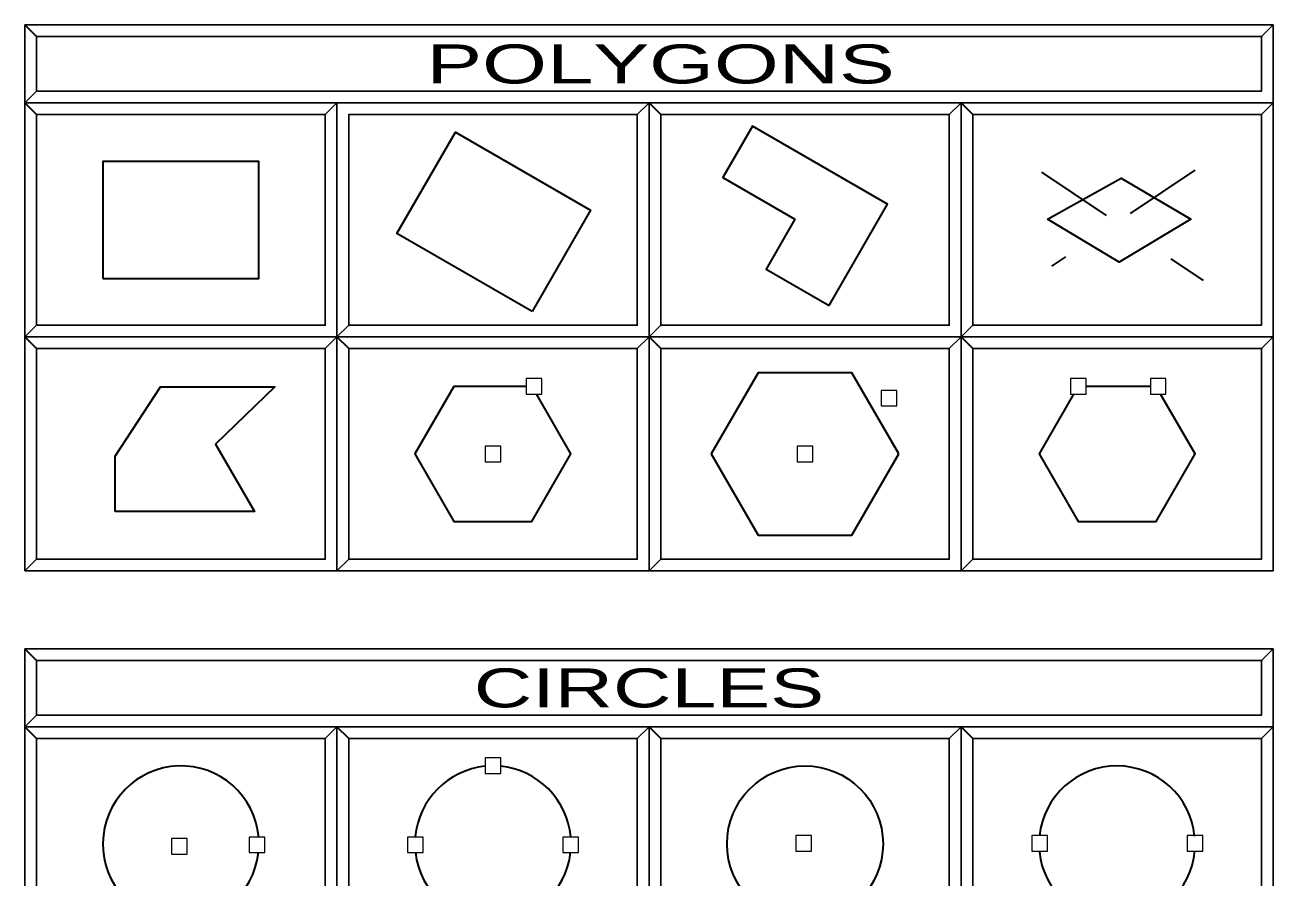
# Model space of a CAD drawing. Extents: x 95906.9 to 95918.9, y 90964.8 to 90972.9.
# Drawn here: x 95910.832 to 95912.432, y 90969.669 to 90970.762 of the extents above; entities that cross this region are included whole.
import ezdxf
from ezdxf.enums import TextEntityAlignment as Align

# ---------------------------------------------------------------- set-up
doc = ezdxf.new("R2010")
doc.units = 0
doc.header["$LTSCALE"] = 0.019
doc.linetypes.add('MEDIUM_DASHED', pattern=[4.5, 3, -1.5])
for name, color, linetype, lineweight in [('1', 7, 'Continuous', 25), ('11', 7, 'Continuous', 25), ('12', 7, 'Continuous', 25), ('17', 7, 'Continuous', 25), ('2', 7, 'Continuous', 13), ('3', 7, 'Continuous', 25), ('4', 7, 'Continuous', 35), ('6', 7, 'Continuous', 35), ('7', 7, 'Continuous', 35)]:
    doc.layers.add(name, color=color, linetype=linetype, lineweight=lineweight)

msp = doc.modelspace()

# ---------------------------------------------------------------- linework, layer by layer
at = {"layer": '1'}
for points in [[(95910.8318, 90970.6617), (95912.4318, 90970.6617), (95912.4318, 90970.7617), (95910.8318, 90970.7617)], [(95910.8318, 90970.3617), (95911.2318, 90970.3617), (95911.2318, 90970.6617), (95910.8318, 90970.6617)], [(95911.2318, 90970.3617), (95911.6318, 90970.3617), (95911.6318, 90970.6617), (95911.2318, 90970.6617)], [(95911.6318, 90970.3617), (95912.0318, 90970.3617), (95912.0318, 90970.6617), (95911.6318, 90970.6617)], [(95912.0318, 90970.3617), (95912.4318, 90970.3617), (95912.4318, 90970.6617), (95912.0318, 90970.6617)], [(95910.8318, 90970.0617), (95911.2318, 90970.0617), (95911.2318, 90970.3617), (95910.8318, 90970.3617)], [(95911.2318, 90970.0617), (95911.6318, 90970.0617), (95911.6318, 90970.3617), (95911.2318, 90970.3617)], [(95911.6318, 90970.0617), (95912.0318, 90970.0617), (95912.0318, 90970.3617), (95911.6318, 90970.3617)], [(95912.0318, 90970.0617), (95912.4318, 90970.0617), (95912.4318, 90970.3617), (95912.0318, 90970.3617)], [(95910.8318, 90969.8617), (95912.4318, 90969.8617), (95912.4318, 90969.9617), (95910.8318, 90969.9617)], [(95910.8318, 90969.5617), (95911.2318, 90969.5617), (95911.2318, 90969.8617), (95910.8318, 90969.8617)], [(95911.2318, 90969.5617), (95911.6318, 90969.5617), (95911.6318, 90969.8617), (95911.2318, 90969.8617)], [(95911.6318, 90969.5617), (95912.0318, 90969.5617), (95912.0318, 90969.8617), (95911.6318, 90969.8617)], [(95912.0318, 90969.5617), (95912.4318, 90969.5617), (95912.4318, 90969.8617), (95912.0318, 90969.8617)]]:
    msp.add_lwpolyline(points, close=True, dxfattribs=at)
at = {"layer": '11'}
for points in [[(95910.8468, 90970.3767), (95911.2168, 90970.3767), (95911.2168, 90970.6467), (95910.8468, 90970.6467)], [(95911.2468, 90970.3767), (95911.6168, 90970.3767), (95911.6168, 90970.6467), (95911.2468, 90970.6467)], [(95911.6468, 90970.3767), (95912.0168, 90970.3767), (95912.0168, 90970.6467), (95911.6468, 90970.6467)], [(95912.0468, 90970.3767), (95912.4168, 90970.3767), (95912.4168, 90970.6467), (95912.0468, 90970.6467)], [(95910.8468, 90970.0767), (95911.2168, 90970.0767), (95911.2168, 90970.3467), (95910.8468, 90970.3467)], [(95911.2468, 90970.0767), (95911.6168, 90970.0767), (95911.6168, 90970.3467), (95911.2468, 90970.3467)], [(95911.6468, 90970.0767), (95912.0168, 90970.0767), (95912.0168, 90970.3467), (95911.6468, 90970.3467)], [(95912.0468, 90970.0767), (95912.4168, 90970.0767), (95912.4168, 90970.3467), (95912.0468, 90970.3467)], [(95910.8468, 90969.5767), (95911.2168, 90969.5767), (95911.2168, 90969.8467), (95910.8468, 90969.8467)], [(95911.2468, 90969.5767), (95911.6168, 90969.5767), (95911.6168, 90969.8467), (95911.2468, 90969.8467)], [(95911.6468, 90969.5767), (95912.0168, 90969.5767), (95912.0168, 90969.8467), (95911.6468, 90969.8467)], [(95912.0468, 90969.5767), (95912.4168, 90969.5767), (95912.4168, 90969.8467), (95912.0468, 90969.8467)]]:
    msp.add_lwpolyline(points, close=True, dxfattribs=at)
at = {"layer": '12'}
for points in [[(95910.8468, 90970.3767), (95911.2168, 90970.3767), (95911.2168, 90970.6467), (95910.8468, 90970.6467)], [(95910.8468, 90969.5767), (95911.2168, 90969.5767), (95911.2168, 90969.8467), (95910.8468, 90969.8467)]]:
    msp.add_lwpolyline(points, close=True, dxfattribs=at)
at = {"layer": '17'}
for points in [[(95910.8468, 90970.6767), (95912.4168, 90970.6767), (95912.4168, 90970.7467), (95910.8468, 90970.7467)], [(95910.8468, 90969.8767), (95912.4168, 90969.8767), (95912.4168, 90969.9467), (95910.8468, 90969.9467)]]:
    msp.add_lwpolyline(points, close=True, dxfattribs=at)
at = {"layer": '2'}
for points in [[(95910.8318, 90970.7617), (95910.8318, 90970.6617), (95910.8468, 90970.6767), (95910.8468, 90970.7467), (95912.4168, 90970.7467), (95912.4318, 90970.7617)], [(95910.8318, 90970.6617), (95910.8318, 90970.3617), (95910.8468, 90970.3767), (95910.8468, 90970.6467), (95911.2168, 90970.6467), (95911.2318, 90970.6617)], [(95911.2318, 90970.6617), (95911.2318, 90970.3617), (95911.2468, 90970.3767), (95911.2468, 90970.6467), (95911.6168, 90970.6467), (95911.6318, 90970.6617)], [(95911.6318, 90970.6617), (95911.6318, 90970.3617), (95911.6468, 90970.3767), (95911.6468, 90970.6467), (95912.0168, 90970.6467), (95912.0318, 90970.6617)], [(95912.0318, 90970.6617), (95912.0318, 90970.3617), (95912.0468, 90970.3767), (95912.0468, 90970.6467), (95912.4168, 90970.6467), (95912.4318, 90970.6617)], [(95910.8318, 90970.3617), (95910.8318, 90970.0617), (95910.8468, 90970.0767), (95910.8468, 90970.3467), (95911.2168, 90970.3467), (95911.2318, 90970.3617)], [(95911.2318, 90970.3617), (95911.2318, 90970.0617), (95911.2468, 90970.0767), (95911.2468, 90970.3467), (95911.6168, 90970.3467), (95911.6318, 90970.3617)], [(95911.6318, 90970.3617), (95911.6318, 90970.0617), (95911.6468, 90970.0767), (95911.6468, 90970.3467), (95912.0168, 90970.3467), (95912.0318, 90970.3617)], [(95912.0318, 90970.3617), (95912.0318, 90970.0617), (95912.0468, 90970.0767), (95912.0468, 90970.3467), (95912.4168, 90970.3467), (95912.4318, 90970.3617)], [(95910.8318, 90969.9617), (95910.8318, 90969.8617), (95910.8468, 90969.8767), (95910.8468, 90969.9467), (95912.4168, 90969.9467), (95912.4318, 90969.9617)], [(95910.8318, 90969.8617), (95910.8318, 90969.5617), (95910.8468, 90969.5767), (95910.8468, 90969.8467), (95911.2168, 90969.8467), (95911.2318, 90969.8617)], [(95911.2318, 90969.8617), (95911.2318, 90969.5617), (95911.2468, 90969.5767), (95911.2468, 90969.8467), (95911.6168, 90969.8467), (95911.6318, 90969.8617)], [(95911.6318, 90969.8617), (95911.6318, 90969.5617), (95911.6468, 90969.5767), (95911.6468, 90969.8467), (95912.0168, 90969.8467), (95912.0318, 90969.8617)], [(95912.0318, 90969.8617), (95912.0318, 90969.5617), (95912.0468, 90969.5767), (95912.0468, 90969.8467), (95912.4168, 90969.8467), (95912.4318, 90969.8617)]]:
    msp.add_lwpolyline(points, close=True, dxfattribs=at)
at = {"layer": '3'}
for points in [[(95910.8318, 90970.6617), (95912.4318, 90970.6617), (95912.4318, 90970.7617), (95912.4168, 90970.7467), (95912.4168, 90970.6767), (95910.8468, 90970.6767)], [(95910.8318, 90970.3617), (95911.2318, 90970.3617), (95911.2318, 90970.6617), (95911.2168, 90970.6467), (95911.2168, 90970.3767), (95910.8468, 90970.3767)], [(95911.2318, 90970.3617), (95911.6318, 90970.3617), (95911.6318, 90970.6617), (95911.6168, 90970.6467), (95911.6168, 90970.3767), (95911.2468, 90970.3767)], [(95911.6318, 90970.3617), (95912.0318, 90970.3617), (95912.0318, 90970.6617), (95912.0168, 90970.6467), (95912.0168, 90970.3767), (95911.6468, 90970.3767)], [(95912.0318, 90970.3617), (95912.4318, 90970.3617), (95912.4318, 90970.6617), (95912.4168, 90970.6467), (95912.4168, 90970.3767), (95912.0468, 90970.3767)], [(95910.8318, 90970.0617), (95911.2318, 90970.0617), (95911.2318, 90970.3617), (95911.2168, 90970.3467), (95911.2168, 90970.0767), (95910.8468, 90970.0767)], [(95911.2318, 90970.0617), (95911.6318, 90970.0617), (95911.6318, 90970.3617), (95911.6168, 90970.3467), (95911.6168, 90970.0767), (95911.2468, 90970.0767)], [(95911.6318, 90970.0617), (95912.0318, 90970.0617), (95912.0318, 90970.3617), (95912.0168, 90970.3467), (95912.0168, 90970.0767), (95911.6468, 90970.0767)], [(95912.0318, 90970.0617), (95912.4318, 90970.0617), (95912.4318, 90970.3617), (95912.4168, 90970.3467), (95912.4168, 90970.0767), (95912.0468, 90970.0767)], [(95910.8318, 90969.8617), (95912.4318, 90969.8617), (95912.4318, 90969.9617), (95912.4168, 90969.9467), (95912.4168, 90969.8767), (95910.8468, 90969.8767)], [(95910.8318, 90969.5617), (95911.2318, 90969.5617), (95911.2318, 90969.8617), (95911.2168, 90969.8467), (95911.2168, 90969.5767), (95910.8468, 90969.5767)], [(95911.2318, 90969.5617), (95911.6318, 90969.5617), (95911.6318, 90969.8617), (95911.6168, 90969.8467), (95911.6168, 90969.5767), (95911.2468, 90969.5767)], [(95911.6318, 90969.5617), (95912.0318, 90969.5617), (95912.0318, 90969.8617), (95912.0168, 90969.8467), (95912.0168, 90969.5767), (95911.6468, 90969.5767)], [(95912.0318, 90969.5617), (95912.4318, 90969.5617), (95912.4318, 90969.8617), (95912.4168, 90969.8467), (95912.4168, 90969.5767), (95912.0468, 90969.5767)]]:
    msp.add_lwpolyline(points, close=True, dxfattribs=at)
at = {"layer": '4'}
for p, q in [((95910.8468, 90970.7467), (95910.8318, 90970.7617)), ((95910.8468, 90970.6467), (95910.8318, 90970.6617)), ((95911.6468, 90970.6467), (95911.6318, 90970.6617)), ((95912.0468, 90970.6467), (95912.0318, 90970.6617)), ((95910.8468, 90970.3467), (95910.8318, 90970.3617)), ((95911.2468, 90970.3467), (95911.2318, 90970.3617)), ((95911.6468, 90970.3467), (95911.6318, 90970.3617)), ((95912.0468, 90970.3467), (95912.0318, 90970.3617)), ((95910.8468, 90969.9467), (95910.8318, 90969.9617)), ((95910.8468, 90969.8467), (95910.8318, 90969.8617)), ((95911.2468, 90969.8467), (95911.2318, 90969.8617)), ((95911.6468, 90969.8467), (95911.6318, 90969.8617)), ((95912.0468, 90969.8467), (95912.0318, 90969.8617))]:
    msp.add_line(p, q, dxfattribs=at)
at = {"layer": '6', "linetype": 'MEDIUM_DASHED'}
for p, q in [((95912.1349, 90970.5731), (95912.3422, 90970.434)), ((95912.3317, 90970.5757), (95912.148, 90970.4524))]:
    msp.add_line(p, q, dxfattribs=at)
at = {"layer": '6'}
msp.add_line((95912.2746, 90970.2983), (95912.1929, 90970.2983), dxfattribs=at)
for points in [[(95911.4819, 90970.3944), (95911.3087, 90970.4944), (95911.3837, 90970.6243), (95911.5569, 90970.5243)], [(95911.8627, 90970.4021), (95911.9377, 90970.532), (95911.7645, 90970.632), (95911.7264, 90970.566), (95911.8188, 90970.5127), (95911.7819, 90970.4488)], [(95910.9318, 90970.4367), (95911.1318, 90970.4367), (95911.1318, 90970.5867), (95910.9318, 90970.5867)], [(95912.1428, 90970.5127), (95912.2372, 90970.5652), (95912.3264, 90970.5127), (95912.2346, 90970.4576)], [(95911.952, 90970.2117), (95911.8919, 90970.3158), (95911.7717, 90970.3158), (95911.7116, 90970.2117), (95911.7717, 90970.1076), (95911.8919, 90970.1076)], [(95910.9476, 90970.1378), (95910.9476, 90970.2087), (95911.0054, 90970.2979), (95911.1523, 90970.2979), (95911.0762, 90970.2244), (95911.126, 90970.1378)]]:
    msp.add_lwpolyline(points, close=True, dxfattribs=at)
at = {"layer": '6', "lineweight": 13}
for points in [[(95911.4743, 90970.2883), (95911.4943, 90970.2883), (95911.4943, 90970.3083), (95911.4743, 90970.3083)], [(95912.1722, 90970.2883), (95912.1922, 90970.2883), (95912.1922, 90970.3083), (95912.1722, 90970.3083)], [(95912.2745, 90970.2883), (95912.2945, 90970.2883), (95912.2945, 90970.3083), (95912.2745, 90970.3083)], [(95911.9294, 90970.2732), (95911.9494, 90970.2732), (95911.9494, 90970.2932), (95911.9294, 90970.2932)], [(95911.4218, 90970.2017), (95911.4418, 90970.2017), (95911.4418, 90970.2217), (95911.4218, 90970.2217)], [(95911.8218, 90970.2017), (95911.8418, 90970.2017), (95911.8418, 90970.2217), (95911.8218, 90970.2217)], [(95911.4217, 90969.8019), (95911.4417, 90969.8019), (95911.4417, 90969.8219), (95911.4217, 90969.8219)], [(95911.0196, 90969.6985), (95911.0396, 90969.6985), (95911.0396, 90969.7185), (95911.0196, 90969.7185)], [(95911.1192, 90969.7005), (95911.1392, 90969.7005), (95911.1392, 90969.7205), (95911.1192, 90969.7205)], [(95911.3221, 90969.7005), (95911.3421, 90969.7005), (95911.3421, 90969.7205), (95911.3221, 90969.7205)], [(95911.5213, 90969.7005), (95911.5413, 90969.7005), (95911.5413, 90969.7205), (95911.5213, 90969.7205)], [(95911.82, 90969.7024), (95911.84, 90969.7024), (95911.84, 90969.7224), (95911.82, 90969.7224)], [(95912.1225, 90969.7024), (95912.1425, 90969.7024), (95912.1425, 90969.7224), (95912.1225, 90969.7224)], [(95912.3217, 90969.7024), (95912.3417, 90969.7024), (95912.3417, 90969.7224), (95912.3217, 90969.7224)]]:
    msp.add_lwpolyline(points, close=True, dxfattribs=at)
at = {"layer": '6'}
for points in [[(95911.4742, 90970.2983), (95911.3818, 90970.2983), (95911.3318, 90970.2117), (95911.3818, 90970.1251), (95911.4818, 90970.1251), (95911.5318, 90970.2117), (95911.4879, 90970.2878)], [(95912.1761, 90970.2884), (95912.1318, 90970.2117), (95912.1818, 90970.1251), (95912.2818, 90970.1251), (95912.3318, 90970.2117), (95912.2876, 90970.2883)]]:
    msp.add_lwpolyline(points, dxfattribs=at)
msp.add_circle((95911.8318, 90969.7117), 0.1, dxfattribs=at)
for centre, start, end in [((95911.0318, 90969.7117), 4.8874, 353.6041), ((95911.4318, 90969.7117), 95.8922, 174.6455), ((95911.4318, 90969.7117), 5.1844, 84.3911), ((95912.2318, 90969.7117), 5.5709, 173.9917), ((95911.4318, 90969.7117), 186.3938, 353.698), ((95912.2318, 90969.7117), 185.8843, 354.917)]:
    msp.add_arc(centre, 0.1, start, end, dxfattribs=at)

# ---------------------------------------------------------------- texts
at = {"layer": '7'}
for s, width, p in [('        POLYGONS       ', 1.6, (95911.6318, 90970.6867)), ('        CIRCLES        ', 1.55, (95911.6318, 90969.8867))]:
    msp.add_text(s, height=0.04999, dxfattribs=dict(at, width=width)).set_placement(p, align=Align.CENTER)

doc.saveas('drawing.dxf')
